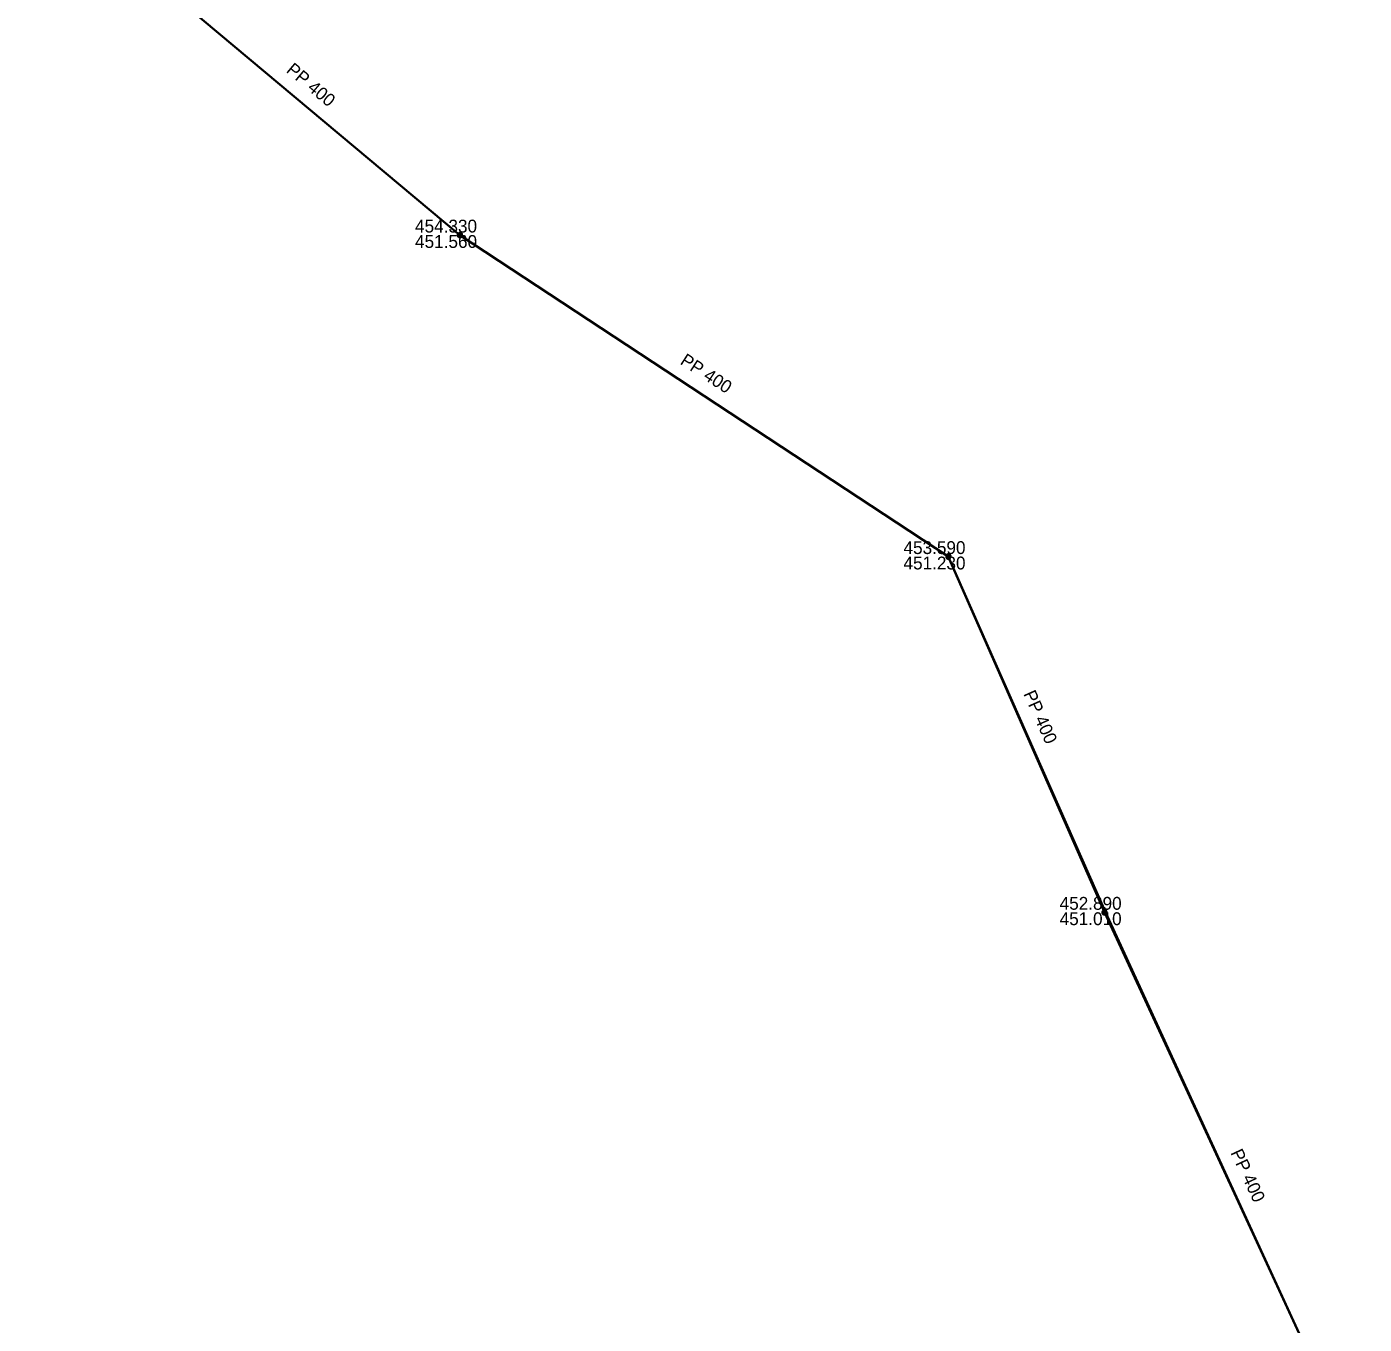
# Model space of a CAD drawing. Extents: x -873619 to -867639, y -1015082 to -1012326.
# Drawn here: x -873191.6 to -873076.9, y -1013760 to -1013648.8 of the extents above; entities that cross this region are included whole.
import ezdxf

# ---------------------------------------------------------------- set-up
doc = ezdxf.new("R2010")
doc.units = 0
doc.header["$LTSCALE"] = 0.44
for name, color, linetype, lineweight in [('1', 7, 'Continuous', 13), ('21', 7, 'Continuous', 35), ('3', 7, 'Continuous', 25), ('32', 7, 'Continuous', 13)]:
    doc.layers.add(name, color=color, linetype=linetype, lineweight=lineweight)

msp = doc.modelspace()

# ---------------------------------------------------------------- linework, layer by layer
at = {"layer": '21'}
for p, q in [((-873180.8, -1013644.59), (-873154.47, -1013666.63)), ((-873154.47, -1013666.63), (-873112.58, -1013694.19)), ((-873112.58, -1013694.19), (-873099.19, -1013724.68)), ((-873099.19, -1013724.68), (-873076.92, -1013772.84))]:
    msp.add_line(p, q, dxfattribs=at)
at = {"layer": '3'}
msp.add_lwpolyline([(-873209.421, -1014292.661), (-873208.998, -1014240.45), (-873211.448, -1014197.31), (-873215.58, -1014166.03), (-873205.44, -1014160.07), (-873195.92, -1014151.84), (-873190.998, -1014149.15), (-873189.02, -1014105.45), (-873184.64, -1014067), (-873178.998, -1014022.35), (-873173.208, -1014002.85), (-873150.578, -1013958.19), (-873123.56, -1013906.71), (-873116.49, -1013857.17), (-873096.298, -1013812.05), (-873076.908, -1013772.84), (-873099.08, -1013724.68), (-873112.568, -1013694.19), (-873154.458, -1013666.63), (-873180.788, -1013644.59), (-873224.641, -1013607.538), (-873251.958, -1013559.37), (-873281.448, -1013506.61), (-873307.717, -1013457.772)], dxfattribs=at)
at = {"layer": '32'}
for points in [[(-873154.228, -1013666.63), (-873154.234, -1013666.578), (-873154.251, -1013666.528), (-873154.28, -1013666.484), (-873154.317, -1013666.447), (-873154.362, -1013666.42), (-873154.412, -1013666.403), (-873154.465, -1013666.399), (-873154.517, -1013666.406), (-873154.566, -1013666.425), (-873154.609, -1013666.454), (-873154.645, -1013666.493), (-873154.671, -1013666.538), (-873154.687, -1013666.589), (-873154.69, -1013666.641), (-873154.682, -1013666.693), (-873154.662, -1013666.742), (-873154.631, -1013666.785), (-873154.592, -1013666.819), (-873154.546, -1013666.845), (-873154.495, -1013666.859), (-873154.442, -1013666.861), (-873154.391, -1013666.851), (-873154.343, -1013666.83), (-873154.3, -1013666.799), (-873154.266, -1013666.758), (-873154.242, -1013666.712), (-873154.23, -1013666.661)], [(-873154.258, -1013666.63), (-873154.264, -1013666.581), (-873154.281, -1013666.535), (-873154.309, -1013666.495), (-873154.346, -1013666.463), (-873154.39, -1013666.441), (-873154.438, -1013666.43), (-873154.487, -1013666.43), (-873154.534, -1013666.443), (-873154.577, -1013666.467), (-873154.613, -1013666.5), (-873154.64, -1013666.541), (-873154.656, -1013666.588), (-873154.66, -1013666.637), (-873154.653, -1013666.685), (-873154.634, -1013666.73), (-873154.604, -1013666.77), (-873154.566, -1013666.801), (-873154.522, -1013666.821), (-873154.474, -1013666.831), (-873154.425, -1013666.829), (-873154.378, -1013666.814), (-873154.335, -1013666.789), (-873154.301, -1013666.755), (-873154.275, -1013666.713), (-873154.261, -1013666.666)], [(-873154.288, -1013666.63), (-873154.294, -1013666.585), (-873154.311, -1013666.543), (-873154.339, -1013666.508), (-873154.375, -1013666.481), (-873154.417, -1013666.464), (-873154.462, -1013666.459), (-873154.507, -1013666.465), (-873154.548, -1013666.484), (-873154.583, -1013666.512), (-873154.61, -1013666.549), (-873154.626, -1013666.591), (-873154.63, -1013666.636), (-873154.623, -1013666.681), (-873154.604, -1013666.722), (-873154.575, -1013666.756), (-873154.538, -1013666.782), (-873154.495, -1013666.798), (-873154.45, -1013666.801), (-873154.405, -1013666.793), (-873154.365, -1013666.773), (-873154.331, -1013666.744), (-873154.305, -1013666.706), (-873154.291, -1013666.663)], [(-873154.318, -1013666.63), (-873154.323, -1013666.589), (-873154.341, -1013666.552), (-873154.368, -1013666.521), (-873154.403, -1013666.5), (-873154.443, -1013666.489), (-873154.484, -1013666.491), (-873154.523, -1013666.504), (-873154.557, -1013666.528), (-873154.582, -1013666.56), (-873154.597, -1013666.598), (-873154.6, -1013666.639), (-873154.592, -1013666.679), (-873154.572, -1013666.715), (-873154.543, -1013666.744), (-873154.506, -1013666.763), (-873154.466, -1013666.771), (-873154.425, -1013666.767), (-873154.387, -1013666.752), (-873154.355, -1013666.726), (-873154.332, -1013666.692), (-873154.319, -1013666.653)], [(-873154.348, -1013666.63), (-873154.353, -1013666.594), (-873154.371, -1013666.562), (-873154.397, -1013666.537), (-873154.431, -1013666.522), (-873154.467, -1013666.519), (-873154.502, -1013666.527), (-873154.533, -1013666.547), (-873154.556, -1013666.575), (-873154.569, -1013666.609), (-873154.569, -1013666.646), (-873154.558, -1013666.681), (-873154.537, -1013666.71), (-873154.507, -1013666.731), (-873154.472, -1013666.741), (-873154.435, -1013666.739), (-873154.401, -1013666.725), (-873154.374, -1013666.702), (-873154.355, -1013666.67), (-873154.348, -1013666.635)], [(-873154.378, -1013666.63), (-873154.383, -1013666.599), (-873154.4, -1013666.573), (-873154.426, -1013666.556), (-873154.456, -1013666.549), (-873154.487, -1013666.553), (-873154.514, -1013666.57), (-873154.532, -1013666.594), (-873154.54, -1013666.625), (-873154.536, -1013666.655), (-873154.521, -1013666.683), (-873154.497, -1013666.702), (-873154.467, -1013666.711), (-873154.436, -1013666.708), (-873154.408, -1013666.694), (-873154.388, -1013666.67), (-873154.378, -1013666.641)], [(-873154.408, -1013666.63), (-873154.413, -1013666.606), (-873154.43, -1013666.588), (-873154.453, -1013666.579), (-873154.477, -1013666.582), (-873154.498, -1013666.596), (-873154.509, -1013666.618), (-873154.509, -1013666.643), (-873154.497, -1013666.664), (-873154.477, -1013666.678), (-873154.452, -1013666.681), (-873154.429, -1013666.672), (-873154.413, -1013666.654)], [(-873154.438, -1013666.63), (-873154.443, -1013666.615), (-873154.458, -1013666.609), (-873154.473, -1013666.613), (-873154.48, -1013666.627), (-873154.476, -1013666.642), (-873154.463, -1013666.651), (-873154.448, -1013666.648), (-873154.438, -1013666.636)], [(-873112.338, -1013694.19), (-873112.345, -1013694.138), (-873112.362, -1013694.088), (-873112.391, -1013694.044), (-873112.428, -1013694.007), (-873112.473, -1013693.98), (-873112.522, -1013693.963), (-873112.576, -1013693.959), (-873112.627, -1013693.966), (-873112.676, -1013693.985), (-873112.72, -1013694.014), (-873112.755, -1013694.053), (-873112.782, -1013694.098), (-873112.798, -1013694.149), (-873112.801, -1013694.201), (-873112.793, -1013694.253), (-873112.772, -1013694.302), (-873112.742, -1013694.345), (-873112.703, -1013694.379), (-873112.657, -1013694.405), (-873112.605, -1013694.419), (-873112.553, -1013694.421), (-873112.502, -1013694.411), (-873112.453, -1013694.39), (-873112.411, -1013694.359), (-873112.377, -1013694.318), (-873112.353, -1013694.272), (-873112.34, -1013694.221)], [(-873112.369, -1013694.19), (-873112.375, -1013694.141), (-873112.392, -1013694.095), (-873112.419, -1013694.055), (-873112.456, -1013694.023), (-873112.5, -1013694.001), (-873112.549, -1013693.99), (-873112.598, -1013693.99), (-873112.644, -1013694.003), (-873112.688, -1013694.027), (-873112.723, -1013694.06), (-873112.75, -1013694.101), (-873112.767, -1013694.148), (-873112.771, -1013694.197), (-873112.764, -1013694.245), (-873112.745, -1013694.29), (-873112.715, -1013694.33), (-873112.676, -1013694.361), (-873112.632, -1013694.381), (-873112.585, -1013694.391), (-873112.536, -1013694.389), (-873112.489, -1013694.374), (-873112.446, -1013694.349), (-873112.411, -1013694.315), (-873112.386, -1013694.273), (-873112.372, -1013694.226)], [(-873112.399, -1013694.19), (-873112.404, -1013694.145), (-873112.421, -1013694.103), (-873112.45, -1013694.068), (-873112.485, -1013694.041), (-873112.527, -1013694.024), (-873112.573, -1013694.019), (-873112.617, -1013694.025), (-873112.659, -1013694.044), (-873112.693, -1013694.072), (-873112.72, -1013694.109), (-873112.737, -1013694.151), (-873112.74, -1013694.196), (-873112.733, -1013694.241), (-873112.715, -1013694.282), (-873112.686, -1013694.316), (-873112.649, -1013694.342), (-873112.605, -1013694.358), (-873112.561, -1013694.361), (-873112.516, -1013694.353), (-873112.475, -1013694.333), (-873112.441, -1013694.304), (-873112.416, -1013694.266), (-873112.402, -1013694.223)], [(-873112.429, -1013694.19), (-873112.433, -1013694.149), (-873112.451, -1013694.112), (-873112.478, -1013694.081), (-873112.514, -1013694.06), (-873112.554, -1013694.049), (-873112.595, -1013694.051), (-873112.634, -1013694.064), (-873112.668, -1013694.088), (-873112.693, -1013694.12), (-873112.708, -1013694.158), (-873112.71, -1013694.199), (-873112.703, -1013694.239), (-873112.683, -1013694.275), (-873112.654, -1013694.304), (-873112.617, -1013694.323), (-873112.576, -1013694.331), (-873112.536, -1013694.327), (-873112.497, -1013694.312), (-873112.465, -1013694.286), (-873112.443, -1013694.252), (-873112.429, -1013694.213)], [(-873112.458, -1013694.19), (-873112.463, -1013694.154), (-873112.482, -1013694.122), (-873112.507, -1013694.097), (-873112.541, -1013694.082), (-873112.578, -1013694.079), (-873112.612, -1013694.087), (-873112.644, -1013694.107), (-873112.666, -1013694.135), (-873112.679, -1013694.169), (-873112.679, -1013694.206), (-873112.669, -1013694.241), (-873112.647, -1013694.27), (-873112.617, -1013694.291), (-873112.583, -1013694.301), (-873112.546, -1013694.299), (-873112.512, -1013694.285), (-873112.485, -1013694.262), (-873112.465, -1013694.23), (-873112.458, -1013694.195)], [(-873112.489, -1013694.19), (-873112.494, -1013694.159), (-873112.511, -1013694.133), (-873112.536, -1013694.116), (-873112.566, -1013694.109), (-873112.598, -1013694.113), (-873112.625, -1013694.13), (-873112.642, -1013694.154), (-873112.651, -1013694.185), (-873112.647, -1013694.215), (-873112.632, -1013694.243), (-873112.607, -1013694.262), (-873112.578, -1013694.271), (-873112.546, -1013694.268), (-873112.519, -1013694.254), (-873112.499, -1013694.23), (-873112.489, -1013694.201)], [(-873112.519, -1013694.19), (-873112.524, -1013694.166), (-873112.541, -1013694.148), (-873112.563, -1013694.139), (-873112.588, -1013694.142), (-873112.608, -1013694.156), (-873112.62, -1013694.178), (-873112.62, -1013694.203), (-873112.607, -1013694.224), (-873112.588, -1013694.238), (-873112.563, -1013694.241), (-873112.539, -1013694.232), (-873112.524, -1013694.214)], [(-873112.549, -1013694.19), (-873112.554, -1013694.175), (-873112.568, -1013694.169), (-873112.583, -1013694.173), (-873112.59, -1013694.187), (-873112.587, -1013694.202), (-873112.573, -1013694.211), (-873112.558, -1013694.208), (-873112.549, -1013694.196)], [(-873098.949, -1013724.68), (-873098.955, -1013724.628), (-873098.972, -1013724.578), (-873099.001, -1013724.534), (-873099.038, -1013724.497), (-873099.083, -1013724.47), (-873099.133, -1013724.453), (-873099.186, -1013724.449), (-873099.238, -1013724.456), (-873099.287, -1013724.475), (-873099.33, -1013724.504), (-873099.366, -1013724.543), (-873099.392, -1013724.588), (-873099.408, -1013724.639), (-873099.411, -1013724.691), (-873099.403, -1013724.743), (-873099.383, -1013724.792), (-873099.352, -1013724.835), (-873099.313, -1013724.869), (-873099.267, -1013724.895), (-873099.216, -1013724.909), (-873099.163, -1013724.911), (-873099.112, -1013724.901), (-873099.064, -1013724.88), (-873099.021, -1013724.849), (-873098.987, -1013724.808), (-873098.963, -1013724.762), (-873098.951, -1013724.711)], [(-873098.979, -1013724.68), (-873098.985, -1013724.631), (-873099.002, -1013724.585), (-873099.03, -1013724.545), (-873099.067, -1013724.513), (-873099.111, -1013724.491), (-873099.159, -1013724.48), (-873099.208, -1013724.48), (-873099.255, -1013724.493), (-873099.298, -1013724.517), (-873099.334, -1013724.55), (-873099.361, -1013724.591), (-873099.377, -1013724.638), (-873099.381, -1013724.687), (-873099.374, -1013724.735), (-873099.355, -1013724.78), (-873099.325, -1013724.82), (-873099.287, -1013724.851), (-873099.243, -1013724.871), (-873099.195, -1013724.881), (-873099.146, -1013724.879), (-873099.099, -1013724.864), (-873099.056, -1013724.839), (-873099.022, -1013724.805), (-873098.996, -1013724.763), (-873098.982, -1013724.716)], [(-873099.009, -1013724.68), (-873099.015, -1013724.635), (-873099.032, -1013724.593), (-873099.06, -1013724.558), (-873099.096, -1013724.531), (-873099.138, -1013724.514), (-873099.183, -1013724.509), (-873099.228, -1013724.515), (-873099.269, -1013724.534), (-873099.304, -1013724.562), (-873099.331, -1013724.599), (-873099.347, -1013724.641), (-873099.351, -1013724.686), (-873099.344, -1013724.731), (-873099.325, -1013724.772), (-873099.296, -1013724.806), (-873099.259, -1013724.832), (-873099.216, -1013724.848), (-873099.171, -1013724.851), (-873099.126, -1013724.843), (-873099.086, -1013724.823), (-873099.052, -1013724.794), (-873099.026, -1013724.756), (-873099.012, -1013724.713)], [(-873099.039, -1013724.68), (-873099.044, -1013724.639), (-873099.062, -1013724.602), (-873099.089, -1013724.571), (-873099.124, -1013724.55), (-873099.164, -1013724.539), (-873099.205, -1013724.541), (-873099.244, -1013724.554), (-873099.278, -1013724.578), (-873099.303, -1013724.61), (-873099.318, -1013724.648), (-873099.321, -1013724.689), (-873099.313, -1013724.729), (-873099.293, -1013724.765), (-873099.264, -1013724.794), (-873099.227, -1013724.813), (-873099.187, -1013724.821), (-873099.146, -1013724.817), (-873099.108, -1013724.802), (-873099.076, -1013724.776), (-873099.053, -1013724.742), (-873099.04, -1013724.703)], [(-873099.069, -1013724.68), (-873099.074, -1013724.644), (-873099.092, -1013724.612), (-873099.118, -1013724.587), (-873099.152, -1013724.572), (-873099.188, -1013724.569), (-873099.223, -1013724.577), (-873099.254, -1013724.597), (-873099.277, -1013724.625), (-873099.29, -1013724.659), (-873099.29, -1013724.696), (-873099.279, -1013724.731), (-873099.258, -1013724.76), (-873099.228, -1013724.781), (-873099.193, -1013724.791), (-873099.156, -1013724.789), (-873099.122, -1013724.775), (-873099.095, -1013724.752), (-873099.076, -1013724.72), (-873099.069, -1013724.685)], [(-873099.099, -1013724.68), (-873099.104, -1013724.649), (-873099.121, -1013724.623), (-873099.147, -1013724.606), (-873099.177, -1013724.599), (-873099.208, -1013724.603), (-873099.235, -1013724.62), (-873099.253, -1013724.644), (-873099.261, -1013724.675), (-873099.257, -1013724.705), (-873099.242, -1013724.733), (-873099.218, -1013724.752), (-873099.188, -1013724.761), (-873099.157, -1013724.758), (-873099.129, -1013724.744), (-873099.109, -1013724.72), (-873099.099, -1013724.691)], [(-873099.129, -1013724.68), (-873099.134, -1013724.656), (-873099.151, -1013724.638), (-873099.174, -1013724.629), (-873099.198, -1013724.632), (-873099.219, -1013724.646), (-873099.23, -1013724.668), (-873099.23, -1013724.693), (-873099.218, -1013724.714), (-873099.198, -1013724.728), (-873099.173, -1013724.731), (-873099.15, -1013724.722), (-873099.134, -1013724.704)], [(-873099.159, -1013724.68), (-873099.164, -1013724.665), (-873099.179, -1013724.659), (-873099.194, -1013724.663), (-873099.201, -1013724.677), (-873099.197, -1013724.692), (-873099.184, -1013724.701), (-873099.169, -1013724.698), (-873099.159, -1013724.686)]]:
    msp.add_lwpolyline(points, close=True, dxfattribs=at)

# ---------------------------------------------------------------- texts
at = {"layer": '1'}
for rotation, p in [(320, (-873169.426, -1013652.609)), (327, (-873135.649, -1013677.634)), (294, (-873106.158, -1013705.95)), (295, (-873088.395, -1013745.281))]:
    msp.add_text('PP 400', height=1.1, rotation=rotation, dxfattribs=at).set_placement(p)
for s, p in [('454.330 ', (-873158.309, -1013666.41)), ('451.560 ', (-873158.309, -1013667.73)), ('453.590 ', (-873116.42, -1013693.97)), ('451.230 ', (-873116.42, -1013695.29)), ('452.890 ', (-873103.03, -1013724.46)), ('451.010 ', (-873103.03, -1013725.78))]:
    msp.add_text(s, height=1.1, dxfattribs=at).set_placement(p)

doc.saveas('drawing.dxf')
